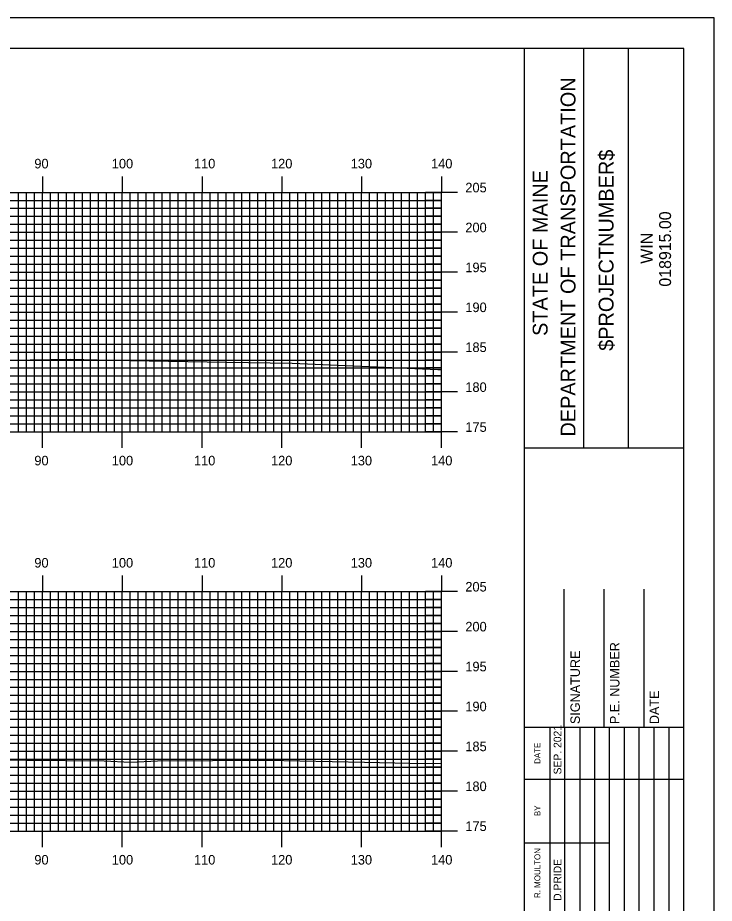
# Model space of a CAD drawing. Extents: x 1808226 to 1808569, y 442591 to 442811.
# Drawn here: x 1808478.2 to 1808565.5, y 442699.6 to 442810.5 of the extents above; entities that cross this region are included whole.
import ezdxf

# ---------------------------------------------------------------- set-up
doc = ezdxf.new("R2010")
doc.units = 0
for name, color, linetype in [('BORDER', 7, 'Continuous'), ('H_V ANNOTATION', 7, 'Continuous'), ('MAJOR', 7, 'Continuous'), ('MINOR', 7, 'Continuous'), ('PLOT BOUNDARY', 7, 'Continuous'), ('S_Roadway_Centerline', 7, 'Continuous')]:
    doc.layers.add(name, color=color, linetype=linetype)

msp = doc.modelspace()

# ---------------------------------------------------------------- linework, layer by layer
at = {"layer": 'BORDER'}
for p, q in [((1808541.7, 442596.67), (1808541.7, 442806.67)), ((1808549.16, 442756.66), (1808549.16, 442806.66)), ((1808554.75, 442756.66), (1808554.75, 442806.66)), ((1808541.7, 442756.65), (1808561.7, 442756.65)), ((1808546.7, 442721.67), (1808546.7, 442738.97)), ((1808551.7, 442721.67), (1808551.7, 442738.97)), ((1808556.7, 442721.67), (1808556.7, 442738.97)), ((1808541.7, 442721.67), (1808561.7, 442721.67))]:
    msp.add_line(p, q, dxfattribs=at)
msp.add_lwpolyline([(1808241.7, 442596.67), (1808561.7, 442596.67), (1808561.7, 442806.67), (1808241.7, 442806.67)], close=True, dxfattribs=at)
for points in [[(1808544.93, 442715.17), (1808544.93, 442721.67)], [(1808546.79, 442686.68), (1808546.79, 442721.67)], [(1808548.66, 442721.67), (1808548.66, 442686.68)], [(1808550.52, 442686.68), (1808550.52, 442721.67)], [(1808552.38, 442686.68), (1808552.38, 442721.67)], [(1808554.25, 442686.68), (1808554.25, 442721.67)], [(1808556.11, 442686.68), (1808556.11, 442721.67)], [(1808557.97, 442686.68), (1808557.97, 442721.67)], [(1808559.84, 442686.68), (1808559.84, 442721.67)], [(1808544.93, 442686.68), (1808544.93, 442720.26)], [(1808541.7, 442715.17), (1808561.7, 442715.17)], [(1808541.7, 442707.17), (1808544.93, 442707.17)], [(1808544.93, 442707.17), (1808552.38, 442707.17)]]:
    msp.add_lwpolyline(points, dxfattribs=at)
at = {"layer": 'MAJOR'}
for p, q in [((1808481.3, 442790.67), (1808481.3, 442788.67)), ((1808491.3, 442790.67), (1808491.3, 442788.67)), ((1808501.3, 442790.67), (1808501.3, 442788.67)), ((1808511.3, 442790.67), (1808511.3, 442788.67)), ((1808521.3, 442790.67), (1808521.3, 442788.67)), ((1808531.3, 442790.67), (1808531.3, 442788.67)), ((1808251.3, 442788.67), (1808531.3, 442788.67)), ((1808251.3, 442788.67), (1808531.3, 442788.67)), ((1808481.3, 442758.67), (1808481.3, 442788.67)), ((1808491.3, 442758.67), (1808491.3, 442788.67)), ((1808501.3, 442758.67), (1808501.3, 442788.67)), ((1808511.3, 442758.67), (1808511.3, 442788.67)), ((1808521.3, 442758.67), (1808521.3, 442788.67)), ((1808533.3, 442788.67), (1808529.29, 442788.67)), ((1808531.3, 442758.67), (1808531.3, 442788.67)), ((1808531.3, 442758.67), (1808531.3, 442788.67)), ((1808251.3, 442783.67), (1808531.3, 442783.67)), ((1808533.3, 442783.67), (1808529.29, 442783.67)), ((1808251.3, 442778.67), (1808531.3, 442778.67)), ((1808533.3, 442778.67), (1808529.29, 442778.67)), ((1808251.3, 442773.67), (1808531.3, 442773.67)), ((1808533.3, 442773.67), (1808529.29, 442773.67)), ((1808251.3, 442768.67), (1808531.3, 442768.67)), ((1808533.3, 442768.67), (1808529.29, 442768.67)), ((1808251.3, 442763.67), (1808531.3, 442763.67)), ((1808533.3, 442763.67), (1808529.29, 442763.67)), ((1808251.3, 442758.67), (1808531.3, 442758.67)), ((1808251.3, 442758.67), (1808531.3, 442758.67)), ((1808481.3, 442756.66), (1808481.3, 442758.67)), ((1808491.3, 442756.66), (1808491.3, 442758.67)), ((1808501.3, 442756.66), (1808501.3, 442758.67)), ((1808511.3, 442756.66), (1808511.3, 442758.67)), ((1808521.3, 442756.66), (1808521.3, 442758.67)), ((1808533.3, 442758.67), (1808529.29, 442758.67)), ((1808531.3, 442756.66), (1808531.3, 442758.67)), ((1808481.3, 442740.67), (1808481.3, 442738.67)), ((1808491.3, 442740.67), (1808491.3, 442738.67)), ((1808501.3, 442740.67), (1808501.3, 442738.67)), ((1808511.3, 442740.67), (1808511.3, 442738.67)), ((1808521.3, 442740.67), (1808521.3, 442738.67)), ((1808531.3, 442740.67), (1808531.3, 442738.67)), ((1808251.3, 442738.67), (1808531.3, 442738.67)), ((1808251.3, 442738.67), (1808531.3, 442738.67)), ((1808481.3, 442708.67), (1808481.3, 442738.67)), ((1808491.3, 442708.67), (1808491.3, 442738.67)), ((1808501.3, 442708.67), (1808501.3, 442738.67)), ((1808511.3, 442708.67), (1808511.3, 442738.67)), ((1808521.3, 442708.67), (1808521.3, 442738.67)), ((1808533.3, 442738.67), (1808529.29, 442738.67)), ((1808531.3, 442708.67), (1808531.3, 442738.67)), ((1808531.3, 442708.67), (1808531.3, 442738.67)), ((1808251.3, 442733.67), (1808531.3, 442733.67)), ((1808533.3, 442733.67), (1808529.29, 442733.67)), ((1808251.3, 442728.67), (1808531.3, 442728.67)), ((1808533.3, 442728.67), (1808529.29, 442728.67)), ((1808251.3, 442723.67), (1808531.3, 442723.67)), ((1808533.3, 442723.67), (1808529.29, 442723.67)), ((1808251.3, 442718.67), (1808531.3, 442718.67)), ((1808533.3, 442718.67), (1808529.29, 442718.67)), ((1808251.3, 442713.67), (1808531.3, 442713.67)), ((1808533.3, 442713.67), (1808529.29, 442713.67)), ((1808251.3, 442708.67), (1808531.3, 442708.67)), ((1808251.3, 442708.67), (1808531.3, 442708.67)), ((1808481.3, 442706.66), (1808481.3, 442708.67)), ((1808491.3, 442706.66), (1808491.3, 442708.67)), ((1808501.3, 442706.66), (1808501.3, 442708.67)), ((1808511.3, 442706.66), (1808511.3, 442708.67)), ((1808521.3, 442706.66), (1808521.3, 442708.67)), ((1808533.3, 442708.67), (1808529.29, 442708.67)), ((1808531.3, 442706.66), (1808531.3, 442708.67))]:
    msp.add_line(p, q, dxfattribs=at)
at = {"layer": 'MINOR'}
for p, q in [((1808478.3, 442758.67), (1808478.3, 442788.67)), ((1808479.3, 442758.67), (1808479.3, 442788.67)), ((1808480.3, 442758.67), (1808480.3, 442788.67)), ((1808482.3, 442758.67), (1808482.3, 442788.67)), ((1808483.3, 442758.67), (1808483.3, 442788.67)), ((1808484.3, 442758.67), (1808484.3, 442788.67)), ((1808485.3, 442758.67), (1808485.3, 442788.67)), ((1808486.3, 442758.67), (1808486.3, 442788.67)), ((1808487.3, 442758.67), (1808487.3, 442788.67)), ((1808488.3, 442758.67), (1808488.3, 442788.67)), ((1808489.3, 442758.67), (1808489.3, 442788.67)), ((1808490.3, 442758.67), (1808490.3, 442788.67)), ((1808492.3, 442758.67), (1808492.3, 442788.67)), ((1808493.3, 442758.67), (1808493.3, 442788.67)), ((1808494.3, 442758.67), (1808494.3, 442788.67)), ((1808495.3, 442758.67), (1808495.3, 442788.67)), ((1808496.3, 442758.67), (1808496.3, 442788.67)), ((1808497.3, 442758.67), (1808497.3, 442788.67)), ((1808498.3, 442758.67), (1808498.3, 442788.67)), ((1808499.3, 442758.67), (1808499.3, 442788.67)), ((1808500.3, 442758.67), (1808500.3, 442788.67)), ((1808502.3, 442758.67), (1808502.3, 442788.67)), ((1808503.3, 442758.67), (1808503.3, 442788.67)), ((1808504.3, 442758.67), (1808504.3, 442788.67)), ((1808505.3, 442758.67), (1808505.3, 442788.67)), ((1808506.3, 442758.67), (1808506.3, 442788.67)), ((1808507.3, 442758.67), (1808507.3, 442788.67)), ((1808508.3, 442758.67), (1808508.3, 442788.67)), ((1808509.3, 442758.67), (1808509.3, 442788.67)), ((1808510.3, 442758.67), (1808510.3, 442788.67)), ((1808512.3, 442758.67), (1808512.3, 442788.67)), ((1808513.3, 442758.67), (1808513.3, 442788.67)), ((1808514.3, 442758.67), (1808514.3, 442788.67)), ((1808515.3, 442758.67), (1808515.3, 442788.67)), ((1808516.3, 442758.67), (1808516.3, 442788.67)), ((1808517.3, 442758.67), (1808517.3, 442788.67)), ((1808518.3, 442758.67), (1808518.3, 442788.67)), ((1808519.3, 442758.67), (1808519.3, 442788.67)), ((1808520.3, 442758.67), (1808520.3, 442788.67)), ((1808522.3, 442758.67), (1808522.3, 442788.67)), ((1808523.3, 442758.67), (1808523.3, 442788.67)), ((1808524.3, 442758.67), (1808524.3, 442788.67)), ((1808525.3, 442758.67), (1808525.3, 442788.67)), ((1808526.3, 442758.67), (1808526.3, 442788.67)), ((1808527.3, 442758.67), (1808527.3, 442788.67)), ((1808528.3, 442758.67), (1808528.3, 442788.67)), ((1808529.3, 442758.67), (1808529.3, 442788.67)), ((1808530.3, 442758.67), (1808530.3, 442788.67)), ((1808251.3, 442787.67), (1808531.3, 442787.67)), ((1808531.3, 442787.67), (1808529.29, 442787.67)), ((1808251.3, 442786.67), (1808531.3, 442786.67)), ((1808531.3, 442786.67), (1808529.29, 442786.67)), ((1808251.3, 442785.67), (1808531.3, 442785.67)), ((1808531.3, 442785.67), (1808529.29, 442785.67)), ((1808251.3, 442784.67), (1808531.3, 442784.67)), ((1808531.3, 442784.67), (1808529.29, 442784.67)), ((1808251.3, 442782.67), (1808531.3, 442782.67)), ((1808531.3, 442782.67), (1808529.29, 442782.67)), ((1808251.3, 442781.67), (1808531.3, 442781.67)), ((1808531.3, 442781.67), (1808529.29, 442781.67)), ((1808251.3, 442780.67), (1808531.3, 442780.67)), ((1808531.3, 442780.67), (1808529.29, 442780.67)), ((1808251.3, 442779.67), (1808531.3, 442779.67)), ((1808531.3, 442779.67), (1808529.29, 442779.67)), ((1808251.3, 442777.67), (1808531.3, 442777.67)), ((1808531.3, 442777.67), (1808529.29, 442777.67)), ((1808251.3, 442776.67), (1808531.3, 442776.67)), ((1808531.3, 442776.67), (1808529.29, 442776.67)), ((1808251.3, 442775.67), (1808531.3, 442775.67)), ((1808531.3, 442775.67), (1808529.29, 442775.67)), ((1808251.3, 442774.67), (1808531.3, 442774.67)), ((1808531.3, 442774.67), (1808529.29, 442774.67)), ((1808251.3, 442772.67), (1808531.3, 442772.67)), ((1808531.3, 442772.67), (1808529.29, 442772.67)), ((1808251.3, 442771.67), (1808531.3, 442771.67)), ((1808531.3, 442771.67), (1808529.29, 442771.67)), ((1808251.3, 442770.67), (1808531.3, 442770.67)), ((1808531.3, 442770.67), (1808529.29, 442770.67)), ((1808251.3, 442769.67), (1808531.3, 442769.67)), ((1808531.3, 442769.67), (1808529.29, 442769.67)), ((1808251.3, 442767.67), (1808531.3, 442767.67)), ((1808531.3, 442767.67), (1808529.29, 442767.67)), ((1808251.3, 442766.67), (1808531.3, 442766.67)), ((1808531.3, 442766.67), (1808529.29, 442766.67)), ((1808251.3, 442765.67), (1808531.3, 442765.67)), ((1808531.3, 442765.67), (1808529.29, 442765.67)), ((1808251.3, 442764.67), (1808531.3, 442764.67)), ((1808531.3, 442764.67), (1808529.29, 442764.67)), ((1808251.3, 442762.67), (1808531.3, 442762.67)), ((1808531.3, 442762.67), (1808529.29, 442762.67)), ((1808251.3, 442761.67), (1808531.3, 442761.67)), ((1808531.3, 442761.67), (1808529.29, 442761.67)), ((1808251.3, 442760.67), (1808531.3, 442760.67)), ((1808531.3, 442760.67), (1808529.29, 442760.67)), ((1808251.3, 442759.67), (1808531.3, 442759.67)), ((1808531.3, 442759.67), (1808529.29, 442759.67)), ((1808478.3, 442708.67), (1808478.3, 442738.67)), ((1808479.3, 442708.67), (1808479.3, 442738.67)), ((1808480.3, 442708.67), (1808480.3, 442738.67)), ((1808482.3, 442708.67), (1808482.3, 442738.67)), ((1808483.3, 442708.67), (1808483.3, 442738.67)), ((1808484.3, 442708.67), (1808484.3, 442738.67)), ((1808485.3, 442708.67), (1808485.3, 442738.67)), ((1808486.3, 442708.67), (1808486.3, 442738.67)), ((1808487.3, 442708.67), (1808487.3, 442738.67)), ((1808488.3, 442708.67), (1808488.3, 442738.67)), ((1808489.3, 442708.67), (1808489.3, 442738.67)), ((1808490.3, 442708.67), (1808490.3, 442738.67)), ((1808492.3, 442708.67), (1808492.3, 442738.67)), ((1808493.3, 442708.67), (1808493.3, 442738.67)), ((1808494.3, 442708.67), (1808494.3, 442738.67)), ((1808495.3, 442708.67), (1808495.3, 442738.67)), ((1808496.3, 442708.67), (1808496.3, 442738.67)), ((1808497.3, 442708.67), (1808497.3, 442738.67)), ((1808498.3, 442708.67), (1808498.3, 442738.67)), ((1808499.3, 442708.67), (1808499.3, 442738.67)), ((1808500.3, 442708.67), (1808500.3, 442738.67)), ((1808502.3, 442708.67), (1808502.3, 442738.67)), ((1808503.3, 442708.67), (1808503.3, 442738.67)), ((1808504.3, 442708.67), (1808504.3, 442738.67)), ((1808505.3, 442708.67), (1808505.3, 442738.67)), ((1808506.3, 442708.67), (1808506.3, 442738.67)), ((1808507.3, 442708.67), (1808507.3, 442738.67)), ((1808508.3, 442708.67), (1808508.3, 442738.67)), ((1808509.3, 442708.67), (1808509.3, 442738.67)), ((1808510.3, 442708.67), (1808510.3, 442738.67)), ((1808512.3, 442708.67), (1808512.3, 442738.67)), ((1808513.3, 442708.67), (1808513.3, 442738.67)), ((1808514.3, 442708.67), (1808514.3, 442738.67)), ((1808515.3, 442708.67), (1808515.3, 442738.67)), ((1808516.3, 442708.67), (1808516.3, 442738.67)), ((1808517.3, 442708.67), (1808517.3, 442738.67)), ((1808518.3, 442708.67), (1808518.3, 442738.67)), ((1808519.3, 442708.67), (1808519.3, 442738.67)), ((1808520.3, 442708.67), (1808520.3, 442738.67)), ((1808522.3, 442708.67), (1808522.3, 442738.67)), ((1808523.3, 442708.67), (1808523.3, 442738.67)), ((1808524.3, 442708.67), (1808524.3, 442738.67)), ((1808525.3, 442708.67), (1808525.3, 442738.67)), ((1808526.3, 442708.67), (1808526.3, 442738.67)), ((1808527.3, 442708.67), (1808527.3, 442738.67)), ((1808528.3, 442708.67), (1808528.3, 442738.67)), ((1808529.3, 442708.67), (1808529.3, 442738.67)), ((1808530.3, 442708.67), (1808530.3, 442738.67)), ((1808251.3, 442737.67), (1808531.3, 442737.67)), ((1808531.3, 442737.67), (1808529.29, 442737.67)), ((1808251.3, 442736.67), (1808531.3, 442736.67)), ((1808531.3, 442736.67), (1808529.29, 442736.67)), ((1808251.3, 442735.67), (1808531.3, 442735.67)), ((1808531.3, 442735.67), (1808529.29, 442735.67)), ((1808251.3, 442734.67), (1808531.3, 442734.67)), ((1808531.3, 442734.67), (1808529.29, 442734.67)), ((1808251.3, 442732.67), (1808531.3, 442732.67)), ((1808251.3, 442731.67), (1808531.3, 442731.67)), ((1808531.3, 442732.67), (1808529.29, 442732.67)), ((1808531.3, 442731.67), (1808529.29, 442731.67)), ((1808251.3, 442730.67), (1808531.3, 442730.67)), ((1808531.3, 442730.67), (1808529.29, 442730.67)), ((1808251.3, 442729.67), (1808531.3, 442729.67)), ((1808531.3, 442729.67), (1808529.29, 442729.67)), ((1808251.3, 442727.67), (1808531.3, 442727.67)), ((1808531.3, 442727.67), (1808529.29, 442727.67)), ((1808251.3, 442726.67), (1808531.3, 442726.67)), ((1808531.3, 442726.67), (1808529.29, 442726.67)), ((1808251.3, 442725.67), (1808531.3, 442725.67)), ((1808531.3, 442725.67), (1808529.29, 442725.67)), ((1808251.3, 442724.67), (1808531.3, 442724.67)), ((1808531.3, 442724.67), (1808529.29, 442724.67)), ((1808251.3, 442722.67), (1808531.3, 442722.67)), ((1808251.3, 442721.67), (1808531.3, 442721.67)), ((1808531.3, 442722.67), (1808529.29, 442722.67)), ((1808531.3, 442721.67), (1808529.29, 442721.67)), ((1808251.3, 442720.67), (1808531.3, 442720.67)), ((1808531.3, 442720.67), (1808529.29, 442720.67)), ((1808251.3, 442719.67), (1808531.3, 442719.67)), ((1808531.3, 442719.67), (1808529.29, 442719.67)), ((1808251.3, 442717.67), (1808531.3, 442717.67)), ((1808531.3, 442717.67), (1808529.29, 442717.67)), ((1808251.3, 442716.67), (1808531.3, 442716.67)), ((1808531.3, 442716.67), (1808529.29, 442716.67)), ((1808251.3, 442715.67), (1808531.3, 442715.67)), ((1808531.3, 442715.67), (1808529.29, 442715.67)), ((1808251.3, 442714.67), (1808531.3, 442714.67)), ((1808531.3, 442714.67), (1808529.29, 442714.67)), ((1808251.3, 442712.67), (1808531.3, 442712.67)), ((1808251.3, 442711.67), (1808531.3, 442711.67)), ((1808531.3, 442712.67), (1808529.29, 442712.67)), ((1808531.3, 442711.67), (1808529.29, 442711.67)), ((1808251.3, 442710.67), (1808531.3, 442710.67)), ((1808531.3, 442710.67), (1808529.29, 442710.67)), ((1808251.3, 442709.67), (1808531.3, 442709.67)), ((1808531.3, 442709.67), (1808529.29, 442709.67))]:
    msp.add_line(p, q, dxfattribs=at)
at = {"layer": 'PLOT BOUNDARY'}
msp.add_lwpolyline([(1808225.51, 442590.55), (1808565.51, 442590.55), (1808565.51, 442810.55), (1808225.51, 442810.55)], close=True, dxfattribs=at)
at = {"layer": 'S_Roadway_Centerline'}
for points in [[(1808324.68, 442769.2), (1808341.69, 442769.04), (1808350.51, 442768.98), (1808362.69, 442768.77), (1808375.74, 442768.72), (1808380.4, 442768.65), (1808384.37, 442768.55), (1808392.46, 442768.41), (1808401.68, 442768.65), (1808403.84, 442768.71), (1808405.46, 442768.59), (1808426.54, 442767.72), (1808428.01, 442767.72), (1808438.5, 442767.73), (1808448.66, 442767.8), (1808453.86, 442767.8), (1808462.2, 442767.83), (1808469.65, 442767.52), (1808484.82, 442767.78), (1808489.8, 442767.63), (1808504.34, 442767.39), (1808512.6, 442767.29), (1808530.86, 442766.49), (1808531.3, 442766.48)], [(1808339.72, 442720), (1808340.32, 442720), (1808341.08, 442719.99), (1808360.9, 442719.6), (1808366.58, 442719.51), (1808382.67, 442719.22), (1808392.95, 442718.87), (1808399.05, 442718.65), (1808404.19, 442718.59), (1808418.28, 442718.29), (1808422.5, 442718.19), (1808426.22, 442718.09), (1808444.65, 442718.06), (1808446.64, 442718.04), (1808455.66, 442717.85), (1808467.21, 442717.6), (1808469.52, 442717.62), (1808489.02, 442717.46), (1808492.33, 442717.3), (1808495.71, 442717.45), (1808509.49, 442717.54), (1808521.65, 442717.28), (1808527.34, 442717.15), (1808531.3, 442717.12)]]:
    msp.add_lwpolyline(points, dxfattribs=at)

# ---------------------------------------------------------------- texts
at = {"layer": 'BORDER'}
for s, height, p in [('DEPARTMENT OF TRANSPORTATION', 1.8635, (1808548.11, 442758.08)), ('$PROJECTNUMBER$', 1.8635, (1808552.88, 442768.82)), ('STATE OF MAINE', 1.8635, (1808544.61, 442770.69)), ('018915.00', 1.491, (1808560.09, 442776.86)), ('WIN', 1.491, (1808557.77, 442779.73)), ('P.E. NUMBER', 1.1811, (1808553.62, 442722.06)), ('SIGNATURE', 1.181, (1808548.66, 442722.06)), ('DATE', 1.181, (1808558.58, 442722.06)), ('SEP. 2021', 0.969, (1808546.34, 442715.76)), ('DATE', 0.743, (1808543.71, 442717.08)), ('BY', 0.743, (1808543.71, 442710.54)), ('R. MOULTON', 0.745, (1808543.71, 442700.28)), ('D.PRIDE', 0.969, (1808546.34, 442699.92))]:
    msp.add_text(s, height=height, rotation=90, dxfattribs=at).set_placement(p)
at = {"layer": 'H_V ANNOTATION'}
for s, p in [('90', (1808480.27, 442791.67)), ('100', (1808489.98, 442791.67)), ('110', (1808500.28, 442791.67)), ('120', (1808509.94, 442791.67)), ('130', (1808519.93, 442791.67)), ('140', (1808530, 442791.67)), ('205', (1808534.3, 442788.67)), ('200', (1808534.3, 442783.67)), ('195', (1808534.3, 442778.67)), ('190', (1808534.3, 442773.67)), ('185', (1808534.3, 442768.67)), ('180', (1808534.3, 442763.67)), ('175', (1808534.3, 442758.67)), ('90', (1808480.27, 442754.47)), ('100', (1808489.98, 442754.47)), ('110', (1808500.28, 442754.47)), ('120', (1808509.94, 442754.47)), ('130', (1808519.93, 442754.47)), ('140', (1808530, 442754.47)), ('90', (1808480.27, 442741.67)), ('100', (1808489.98, 442741.67)), ('110', (1808500.28, 442741.67)), ('120', (1808509.94, 442741.67)), ('130', (1808519.93, 442741.67)), ('140', (1808530, 442741.67)), ('205', (1808534.3, 442738.67)), ('200', (1808534.3, 442733.67)), ('195', (1808534.3, 442728.67)), ('190', (1808534.3, 442723.67)), ('185', (1808534.3, 442718.67)), ('180', (1808534.3, 442713.67)), ('175', (1808534.3, 442708.67)), ('90', (1808480.27, 442704.47)), ('100', (1808489.98, 442704.47)), ('110', (1808500.28, 442704.47)), ('120', (1808509.94, 442704.47)), ('130', (1808519.93, 442704.47)), ('140', (1808530, 442704.47))]:
    msp.add_text(s, height=1.2, dxfattribs=at).set_placement(p)

doc.saveas('drawing.dxf')
